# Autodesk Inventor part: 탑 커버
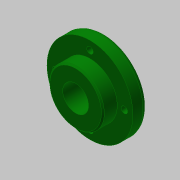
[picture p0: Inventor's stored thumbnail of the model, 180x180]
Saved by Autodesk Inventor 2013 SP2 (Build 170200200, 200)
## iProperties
Created: 2016-08
Part Number: 탑 커버
Material: 알루미늄 6061
Document SubType Name: Modeling
Designer: mduedu
Density: 2.71 g/cm^3
Author: mduedu
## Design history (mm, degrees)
sketch "스케치1"
  geometry: L1 (0, 0)-(0, 10); L2 (0, 10)-(-30, 10); L3 (-30, 10)-(-30, 0); L4 (-30, 0)-(-19, 0); L5 (-19, 0)-(-19, -10); L6 (-19, -10)-(0, -10); L7 (0, -10)-(0, 10); 2 further points
  constraints: 14 end point, 3 parallel, 3 perpendicular, 1 coincident, 1 horizontal alignment, 1 midpoint, 1 vertical
  dimensions: "d0" = 10 distance of L1.start L1.end; "d2" = 60 diameter of L3 L1; "d3" = 38 diameter of L5 L1; "d4" = 20 distance between parallel lines of L6 L2
revolve "회전1" sketch "스케치1" stored, may be unused: angle "d5" = 90 deg
hole "구멍1" diameter "d8" = 18; stored, may be unused: countersink angle "d12" = 90 deg, drill point angle "d14" = 118 deg; dims "d6" = 10, "d7" = 10, "d9" = 6, "d10" = 4, "d11" = 2, "d13" = 8
chamfer "모따기1" distance "d15" = 1; stored, may be unused: second distance "d16" = 2, angle "d17" = 45 deg
chamfer "모따기2" distance "d18" = 1; stored, may be unused: second distance "d19" = 2, angle "d20" = 45 deg
fillet "모깎기1" dims "d21" = 3
sketch "스케치2" dims "d22" = 48
  geometry: 6 further points
  constraints: 2 vertical alignment, 1 coincident, 7 other
  dimensions: "d26" = 360 deg dimension on point (0, 0) point (0, 24) (derived)
sketch "스케치3"
  geometry: 4 further points
hole "구멍2" sketch "스케치3" at (-24, 0), (0, -24), (24, 0), (0, 24) diameter "d28" = 4.5; stored, may be unused: countersink angle "d32" = 90 deg, drill point angle "d34" = 0 deg; dims "d29" = 6, "d30" = 8, "d31" = 4.6, "d33" = 8
node "솔리드1"
